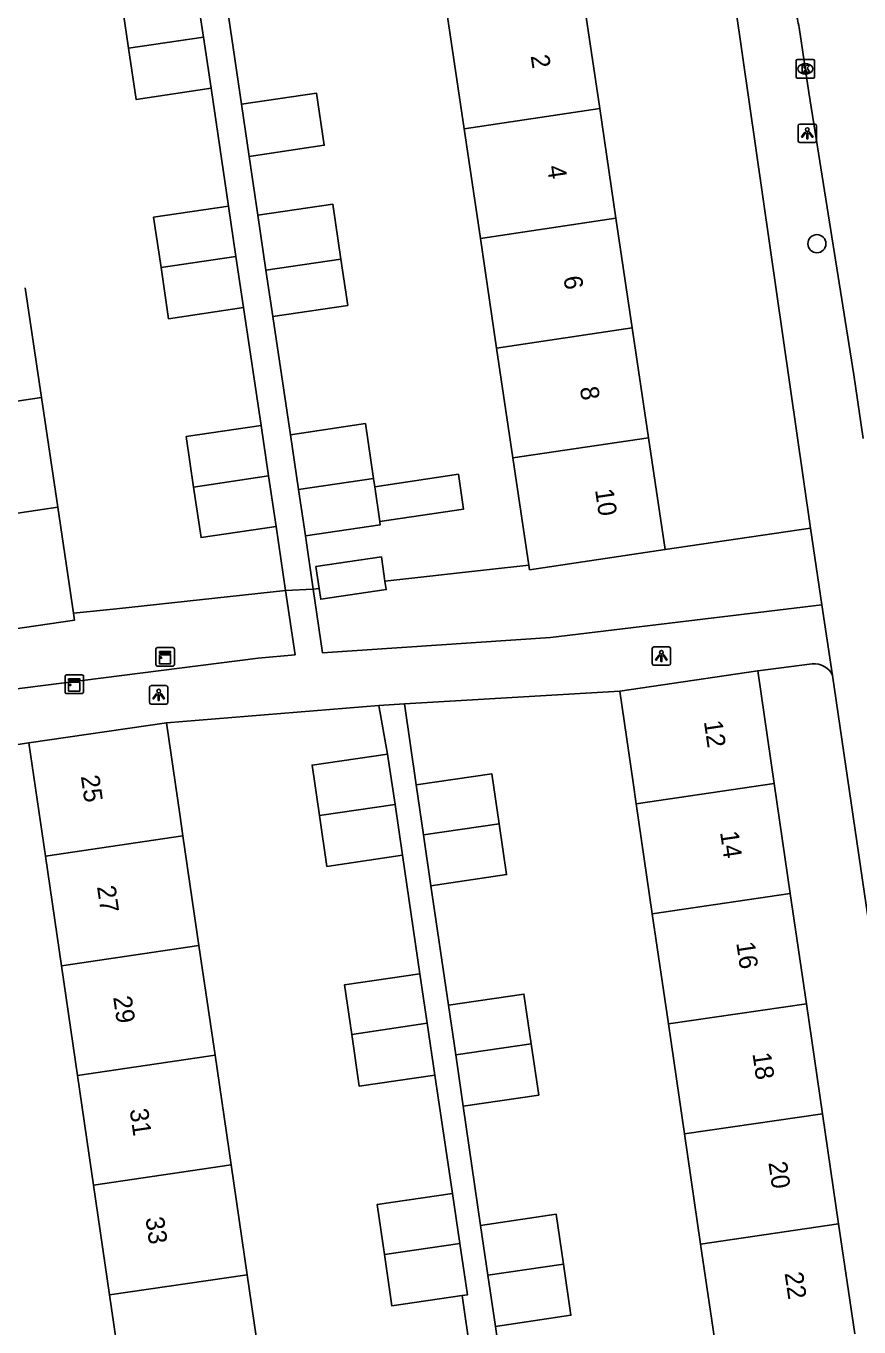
# Model space of a CAD drawing. Extents: x 159053 to 160041, y 380450 to 381422.
# Drawn here: x 159329.7 to 159374.7, y 381049.8 to 381120.2 of the extents above; entities that cross this region are included whole.
import ezdxf

# ---------------------------------------------------------------- set-up
doc = ezdxf.new("R2010")
doc.units = 0
for name, color, linetype in [('IMGEO_Boom', 7, 'Continuous'), ('IMGEO_Groenvoorziening', 7, 'Continuous'), ('IMGEO_Kast', 7, 'Continuous'), ('IMGEO_Kolk', 7, 'Continuous'), ('IMGEO_Lichtpunt', 7, 'Continuous'), ('IMGEO_Muur', 7, 'Continuous'), ('IMGEO_Pand', 7, 'Continuous'), ('IMGEO_Pand_nummerreeks', 7, 'Continuous'), ('IMGEO_Rijbaan_lokaal_open', 7, 'Continuous'), ('IMGEO_Voetpad_open', 7, 'Continuous')]:
    doc.layers.add(name, color=color, linetype=linetype)

msp = doc.modelspace()

# ---------------------------------------------------------------- linework, layer by layer
at = {"layer": 'IMGEO_Boom'}
msp.add_circle((159372.446, 381108.381), 0.489, dxfattribs=at)
at = {"layer": 'IMGEO_Groenvoorziening'}
for points in [[(159372.107, 381092.995), (159364.234, 381091.828)], [(159356.86, 381090.996), (159354.57, 381090.741), (159349.077, 381090.128)], [(159332.23, 381088.384), (159334.548, 381088.632), (159343.701, 381089.611)], [(159345.518, 381089.731), (159345.191, 381089.695)]]:
    msp.add_lwpolyline(points, dxfattribs=at)
at = {"layer": 'IMGEO_Kast'}
for p, q in [((159336.756, 381086.527), (159337.597, 381086.527)), ((159337.597, 381086.527), (159336.756, 381086.527)), ((159336.681, 381085.602), (159336.681, 381086.443)), ((159336.681, 381086.443), (159336.681, 381085.602)), ((159337.681, 381086.452), (159337.681, 381085.611)), ((159337.681, 381085.611), (159337.681, 381086.452)), ((159337.606, 381085.527), (159336.765, 381085.527)), ((159336.765, 381085.527), (159337.606, 381085.527)), ((159331.768, 381084.124), (159331.768, 381084.965)), ((159331.768, 381084.965), (159331.768, 381084.124)), ((159331.843, 381085.049), (159332.684, 381085.049)), ((159332.684, 381085.049), (159331.843, 381085.049)), ((159332.768, 381084.974), (159332.768, 381084.133)), ((159332.768, 381084.133), (159332.768, 381084.974)), ((159332.693, 381084.049), (159331.852, 381084.049)), ((159331.852, 381084.049), (159332.693, 381084.049))]:
    msp.add_line(p, q, dxfattribs=at)
for points in [[(159336.876, 381086.317), (159337.476, 381086.317), (159337.476, 381086.232), (159336.876, 381086.232), (159336.876, 381086.317)], [(159336.876, 381086.142), (159337.476, 381086.142), (159337.476, 381085.653), (159336.876, 381085.653), (159336.876, 381086.142)], [(159331.963, 381084.839), (159332.563, 381084.839), (159332.563, 381084.754), (159331.963, 381084.754), (159331.963, 381084.839)], [(159331.963, 381084.664), (159332.563, 381084.664), (159332.563, 381084.175), (159331.963, 381084.175), (159331.963, 381084.664)]]:
    msp.add_lwpolyline(points, dxfattribs=at)
for centre in [(159336.96, 381085.991), (159332.047, 381084.513)]:
    msp.add_circle(centre, 0.0377, dxfattribs=at)
for centre, start, end in [((159336.759, 381086.449), 92.4484, 184.28452), ((159336.759, 381086.449), 92.4484, 184.28452), ((159337.603, 381086.449), 2.4484, 94.28452), ((159337.603, 381086.449), 2.4484, 94.28452), ((159336.759, 381085.605), 182.4484, 274.28452), ((159336.759, 381085.605), 182.4484, 274.28452), ((159337.603, 381085.605), 272.4484, 4.28452), ((159337.603, 381085.605), 272.4484, 4.28452), ((159331.846, 381084.971), 92.4484, 184.28452), ((159331.846, 381084.971), 92.4484, 184.28452), ((159332.69, 381084.971), 2.4484, 94.28452), ((159332.69, 381084.971), 2.4484, 94.28452), ((159331.846, 381084.127), 182.4484, 274.28452), ((159331.846, 381084.127), 182.4484, 274.28452), ((159332.69, 381084.127), 272.4484, 4.28452), ((159332.69, 381084.127), 272.4484, 4.28452)]:
    msp.add_arc(centre, 0.0779, start, end, dxfattribs=at)
at = {"layer": 'IMGEO_Kolk'}
for p, q in [((159371.32, 381117.416), (159371.32, 381118.268)), ((159371.395, 381118.342), (159372.247, 381118.342)), ((159372.321, 381118.268), (159372.321, 381117.416)), ((159371.831, 381117.562), (159371.806, 381117.562)), ((159371.808, 381118.122), (159371.833, 381118.122)), ((159372.247, 381117.342), (159371.395, 381117.342))]:
    msp.add_line(p, q, dxfattribs=at)
for points in [[(159371.32, 381117.416), (159371.32, 381118.268)], [(159371.395, 381118.342), (159372.247, 381118.342)], [(159372.321, 381118.268), (159372.321, 381117.416)], [(159371.641, 381118.042), (159371.764, 381118.042), (159371.764, 381117.891), (159371.894, 381118.042), (159372.058, 381118.042), (159371.912, 381117.891), (159372.065, 381117.642), (159371.913, 381117.642), (159371.828, 381117.806), (159371.764, 381117.739), (159371.764, 381117.642), (159371.641, 381117.642), (159371.641, 381118.042)], [(159372.247, 381117.342), (159371.395, 381117.342)]]:
    msp.add_lwpolyline(points, dxfattribs=at)
for centre, start, end in [((159371.397, 381118.266), 91.55205, 178.44795), ((159371.397, 381118.266), 91.55205, 178.44795), ((159372.245, 381118.266), 1.55205, 88.44795), ((159372.245, 381118.266), 1.55205, 88.44795), ((159371.397, 381117.418), 181.55205, 268.44795), ((159371.397, 381117.418), 181.55205, 268.44795), ((159372.245, 381117.418), 271.55205, 358.44795), ((159372.245, 381117.418), 271.55205, 358.44795)]:
    msp.add_arc(centre, 0.0765, start, end, dxfattribs=at)
for centre, major_axis, ratio, start_param, end_param in [((159371.807, 381117.842), (-0.387, 0.002), 0.722429, 4.712389, 7.853982), ((159371.832, 381117.842), (-0.39, 0.002), 0.717154, 1.570796, 4.712389)]:
    msp.add_ellipse(centre, major_axis=major_axis, ratio=ratio, start_param=start_param, end_param=end_param, dxfattribs=at)
at = {"layer": 'IMGEO_Lichtpunt'}
for p, q in [((159371.428, 381114.76), (159371.428, 381113.953)), ((159371.428, 381114.76), (159371.428, 381113.953)), ((159372.33, 381114.855), (159371.522, 381114.855)), ((159372.33, 381114.855), (159371.522, 381114.855)), ((159372.424, 381113.953), (159372.424, 381114.76)), ((159372.424, 381113.953), (159372.424, 381114.76)), ((159371.522, 381113.859), (159372.33, 381113.859)), ((159371.522, 381113.859), (159372.33, 381113.859)), ((159364.436, 381086.569), (159363.628, 381086.569)), ((159364.436, 381086.569), (159363.628, 381086.569)), ((159363.534, 381086.474), (159363.534, 381085.667)), ((159363.534, 381086.474), (159363.534, 381085.667)), ((159364.53, 381085.667), (159364.53, 381086.474)), ((159364.53, 381085.667), (159364.53, 381086.474)), ((159363.628, 381085.573), (159364.436, 381085.573)), ((159363.628, 381085.573), (159364.436, 381085.573)), ((159337.238, 381084.469), (159336.43, 381084.469)), ((159337.238, 381084.469), (159336.43, 381084.469)), ((159336.336, 381084.374), (159336.336, 381083.567)), ((159336.336, 381084.374), (159336.336, 381083.567)), ((159337.332, 381083.567), (159337.332, 381084.374)), ((159337.332, 381083.567), (159337.332, 381084.374)), ((159336.43, 381083.473), (159337.238, 381083.473)), ((159336.43, 381083.473), (159337.238, 381083.473))]:
    msp.add_line(p, q, dxfattribs=at)
for points in [[(159371.802, 381114.424), (159371.841, 381114.396), (159371.653, 381114.134), (159371.615, 381114.161), (159371.802, 381114.424)], [(159371.904, 381114.376), (159371.951, 381114.376), (159371.951, 381114.054), (159371.904, 381114.054), (159371.904, 381114.376)], [(159372.014, 381114.396), (159372.052, 381114.423), (159372.239, 381114.161), (159372.2, 381114.133), (159372.014, 381114.396)], [(159363.908, 381086.138), (159363.947, 381086.11), (159363.759, 381085.848), (159363.721, 381085.875), (159363.908, 381086.138)], [(159364.01, 381086.09), (159364.057, 381086.09), (159364.057, 381085.768), (159364.01, 381085.768), (159364.01, 381086.09)], [(159364.12, 381086.11), (159364.158, 381086.137), (159364.345, 381085.875), (159364.306, 381085.847), (159364.12, 381086.11)], [(159336.71, 381084.038), (159336.749, 381084.01), (159336.561, 381083.748), (159336.523, 381083.775), (159336.71, 381084.038)], [(159336.812, 381083.99), (159336.859, 381083.99), (159336.859, 381083.668), (159336.812, 381083.668), (159336.812, 381083.99)], [(159336.922, 381084.01), (159336.96, 381084.037), (159337.147, 381083.775), (159337.108, 381083.747), (159336.922, 381084.01)]]:
    msp.add_lwpolyline(points, dxfattribs=at)
for centre in [(159371.927, 381114.558), (159364.033, 381086.272), (159336.835, 381084.172)]:
    msp.add_circle(centre, 0.0994, dxfattribs=at)
for centre, start, end in [((159371.522, 381114.76), 90, 180), ((159371.522, 381114.76), 90, 180), ((159372.33, 381114.76), 0, 90), ((159372.33, 381114.76), 0, 90), ((159371.522, 381113.953), 180, 270), ((159371.522, 381113.953), 180, 270), ((159372.33, 381113.953), 270, 0), ((159372.33, 381113.953), 270, 360), ((159363.628, 381086.474), 90, 180), ((159363.628, 381086.474), 90, 180), ((159364.436, 381086.474), 0, 90), ((159364.436, 381086.474), 0, 90), ((159363.628, 381085.667), 180, 270), ((159363.628, 381085.667), 180, 270), ((159364.436, 381085.667), 270, 0), ((159364.436, 381085.667), 270, 360), ((159336.43, 381084.374), 90, 180), ((159336.43, 381084.374), 90, 180), ((159337.238, 381084.374), 0, 90), ((159337.238, 381084.374), 0, 90), ((159336.43, 381083.567), 180, 270), ((159336.43, 381083.567), 180, 270), ((159337.238, 381083.567), 270, 0), ((159337.238, 381083.567), 270, 360)]:
    msp.add_arc(centre, 0.0946, start, end, dxfattribs=at)
at = {"layer": 'IMGEO_Muur'}
for points in [[(159361.777, 381084.175), (159350.126, 381083.478)], [(159337.25, 381082.465), (159348.751, 381083.396)]]:
    msp.add_lwpolyline(points, dxfattribs=at)
at = {"layer": 'IMGEO_Pand'}
for points in [[(159335.2, 381118.957), (159334.796, 381121.68), (159338.851, 381122.282)], [(159338.851, 381122.282), (159339.255, 381119.559)], [(159360.696, 381115.69), (159359.798, 381121.745)], [(159352.462, 381120.658), (159353.36, 381114.602)], [(159339.255, 381119.559), (159335.2, 381118.957)], [(159339.666, 381116.792), (159335.611, 381116.19), (159335.2, 381118.957)], [(159339.255, 381119.559), (159339.666, 381116.792)], [(159341.321, 381115.924), (159345.378, 381116.523), (159345.795, 381113.703), (159341.738, 381113.104)], [(159341.738, 381113.104), (159341.321, 381115.924)], [(159360.696, 381115.69), (159353.36, 381114.602)], [(159361.576, 381109.755), (159360.696, 381115.69)], [(159353.36, 381114.602), (159354.24, 381108.667)], [(159346.696, 381107.548), (159346.258, 381110.517), (159342.201, 381109.918)], [(159336.96, 381107.087), (159336.556, 381109.81), (159340.611, 381110.412)], [(159340.611, 381110.412), (159341.015, 381107.689)], [(159342.201, 381109.918), (159342.64, 381106.947)], [(159361.576, 381109.755), (159354.24, 381108.667)], [(159362.456, 381103.82), (159361.576, 381109.755)], [(159354.24, 381108.667), (159355.12, 381102.732)], [(159341.015, 381107.689), (159336.96, 381107.087)], [(159341.426, 381104.922), (159341.015, 381107.689)], [(159336.96, 381107.087), (159337.371, 381104.32), (159341.426, 381104.922)], [(159342.64, 381106.947), (159346.696, 381107.548)], [(159343.009, 381104.447), (159342.64, 381106.947)], [(159346.696, 381107.548), (159347.066, 381105.046), (159343.009, 381104.447)], [(159330.498, 381100.062), (159329.618, 381105.998)], [(159355.12, 381102.732), (159362.456, 381103.82)], [(159363.336, 381097.885), (159362.456, 381103.82)], [(159356, 381096.797), (159355.12, 381102.732)], [(159323.098, 381098.964), (159330.498, 381100.062)], [(159330.498, 381100.062), (159331.378, 381094.127)], [(159338.725, 381095.217), (159338.321, 381097.941), (159342.376, 381098.543)], [(159342.376, 381098.543), (159342.78, 381095.819)], [(159343.961, 381098.048), (159348.018, 381098.647), (159348.456, 381095.678)], [(159344.4, 381095.077), (159343.961, 381098.048)], [(159363.336, 381097.885), (159356, 381096.797)], [(159364.234, 381091.828), (159363.336, 381097.885)], [(159356, 381096.797), (159356.86, 381090.996)], [(159338.725, 381095.217), (159342.78, 381095.819)], [(159342.78, 381095.819), (159343.186, 381093.082)], [(159348.456, 381095.678), (159344.4, 381095.077)], [(159348.522, 381095.235), (159348.456, 381095.678)], [(159348.8, 381093.353), (159353.326, 381094.023), (159353.047, 381095.904), (159348.522, 381095.235)], [(159343.186, 381093.082), (159339.131, 381092.48), (159338.725, 381095.217)], [(159344.769, 381092.577), (159344.4, 381095.077)], [(159348.522, 381095.235), (159348.8, 381093.353)], [(159331.378, 381094.127), (159323.978, 381093.029)], [(159332.23, 381088.384), (159331.378, 381094.127)], [(159344.769, 381092.577), (159348.826, 381093.176), (159348.8, 381093.353)], [(159356.86, 381090.996), (159356.898, 381090.74), (159364.234, 381091.828)], [(159349.077, 381090.128), (159348.885, 381091.432), (159345.344, 381090.909), (159345.518, 381089.731)], [(159349.077, 381090.128), (159349.146, 381089.663), (159345.605, 381089.14), (159345.518, 381089.731)], [(159324.884, 381086.922), (159332.284, 381088.02), (159332.23, 381088.384)], [(159369.242, 381085.268), (159361.777, 381084.175)], [(159369.242, 381085.268), (159370.133, 381079.176)], [(159361.777, 381084.175), (159362.501, 381079.228), (159362.668, 381078.084)], [(159337.25, 381082.465), (159329.808, 381081.376)], [(159338.145, 381076.348), (159337.974, 381077.518), (159337.25, 381082.465)], [(159329.808, 381081.376), (159330.704, 381075.253)], [(159349.222, 381080.771), (159345.136, 381080.173), (159345.537, 381077.436)], [(159349.623, 381078.037), (159349.222, 381080.771)], [(159355.25, 381076.999), (159354.853, 381079.706), (159350.766, 381079.108)], [(159350.766, 381079.108), (159351.162, 381076.401)], [(159362.668, 381078.084), (159370.133, 381079.176)], [(159370.133, 381079.176), (159371.005, 381073.219)], [(159362.668, 381078.084), (159363.54, 381072.127)], [(159345.537, 381077.436), (159349.623, 381078.037)], [(159345.537, 381077.436), (159345.939, 381074.692), (159350.025, 381075.29)], [(159350.025, 381075.29), (159349.623, 381078.037)], [(159355.25, 381076.999), (159351.162, 381076.401)], [(159351.566, 381073.646), (159355.653, 381074.244), (159355.25, 381076.999)], [(159330.704, 381075.253), (159338.145, 381076.348)], [(159339.014, 381070.412), (159338.145, 381076.348)], [(159351.162, 381076.401), (159351.566, 381073.646)], [(159330.704, 381075.253), (159331.572, 381069.317)], [(159363.54, 381072.127), (159371.005, 381073.219)], [(159371.005, 381073.219), (159371.877, 381067.262)], [(159363.54, 381072.127), (159364.412, 381066.17)], [(159339.014, 381070.412), (159331.572, 381069.317)], [(159339.883, 381064.475), (159339.014, 381070.412)], [(159331.572, 381069.317), (159332.441, 381063.38)], [(159350.972, 381068.878), (159346.886, 381068.28), (159347.278, 381065.603)], [(159351.363, 381066.21), (159350.972, 381068.878)], [(159356.993, 381065.085), (159356.598, 381067.779), (159352.511, 381067.181)], [(159352.511, 381067.181), (159352.906, 381064.487)], [(159371.877, 381067.262), (159364.412, 381066.17)], [(159371.877, 381067.262), (159372.748, 381061.306)], [(159347.278, 381065.603), (159351.363, 381066.21)], [(159351.775, 381063.397), (159351.363, 381066.21)], [(159364.412, 381066.17), (159365.283, 381060.214)], [(159347.278, 381065.603), (159347.689, 381062.799), (159351.775, 381063.397)], [(159352.906, 381064.487), (159356.993, 381065.085)], [(159353.311, 381061.719), (159357.398, 381062.317), (159356.993, 381065.085)], [(159339.883, 381064.475), (159332.441, 381063.38)], [(159340.751, 381058.538), (159339.883, 381064.475)], [(159352.906, 381064.487), (159353.311, 381061.719)], [(159332.441, 381063.38), (159333.31, 381057.443)], [(159365.283, 381060.214), (159372.748, 381061.306)], [(159372.748, 381061.306), (159373.62, 381055.349)], [(159365.283, 381060.214), (159366.155, 381054.257)], [(159333.31, 381057.443), (159340.751, 381058.538)], [(159341.62, 381052.601), (159340.751, 381058.538)], [(159334.178, 381051.506), (159333.31, 381057.443)], [(159352.737, 381056.99), (159348.651, 381056.392), (159349.046, 381053.694)], [(159353.132, 381054.295), (159352.737, 381056.99)], [(159358.736, 381053.172), (159358.341, 381055.866), (159354.254, 381055.268)], [(159354.254, 381055.268), (159354.649, 381052.574)], [(159373.62, 381055.349), (159366.155, 381054.257)], [(159373.62, 381055.349), (159374.491, 381049.393)], [(159349.046, 381053.694), (159353.132, 381054.295)], [(159353.257, 381051.468), (159353.54, 381051.509), (159353.132, 381054.295)], [(159366.155, 381054.257), (159367.026, 381048.302)], [(159349.046, 381053.694), (159349.454, 381050.911), (159353.257, 381051.468)], [(159354.649, 381052.574), (159358.736, 381053.172)], [(159355.054, 381049.806), (159359.141, 381050.404), (159358.736, 381053.172)], [(159341.62, 381052.601), (159334.178, 381051.506)], [(159342.489, 381046.664), (159341.62, 381052.601)], [(159354.649, 381052.574), (159355.054, 381049.806)], [(159334.178, 381051.506), (159335.047, 381045.569)]]:
    msp.add_lwpolyline(points, dxfattribs=at)
at = {"layer": 'IMGEO_Rijbaan_lokaal_open'}
msp.add_lwpolyline([(159374.956, 381097.837), (159374.453, 381101.279), (159372.016, 381116.567), (159371.48, 381120.071)], dxfattribs=at)
msp.add_arc((159367.251, 381119.5), 4.267, 7.68473, 20.38776, dxfattribs=at)
at = {"layer": 'IMGEO_Voetpad_open'}
for points in [[(159341.321, 381115.924), (159340.268, 381123.048)], [(159368.043, 381121.201), (159372.107, 381092.995)], [(159339.666, 381116.792), (159340.611, 381110.412)], [(159342.201, 381109.918), (159341.738, 381113.104)], [(159341.426, 381104.922), (159342.376, 381098.543)], [(159343.961, 381098.048), (159343.009, 381104.447)], [(159343.186, 381093.082), (159343.701, 381089.611)], [(159372.706, 381088.84), (159372.107, 381092.995)], [(159345.191, 381089.695), (159344.769, 381092.577)], [(159343.701, 381089.611), (159344.216, 381086.143), (159342.223, 381085.964), (159323.192, 381083.535)], [(159343.701, 381089.611), (159345.191, 381089.695)], [(159345.191, 381089.695), (159345.703, 381086.245), (159358.026, 381087.077), (159372.706, 381088.84)], [(159373.296, 381085.027), (159372.706, 381088.84)], [(159372.195, 381085.642), (159369.242, 381085.268)], [(159388.726, 380978.358), (159385.752, 381000), (159373.296, 381085.027)], [(159350.126, 381083.478), (159361.777, 381084.175)], [(159337.25, 381082.465), (159348.751, 381083.396)], [(159348.751, 381083.396), (159350.126, 381083.478)], [(159348.751, 381083.396), (159349.222, 381080.771)], [(159350.766, 381079.108), (159350.126, 381083.478)], [(159329.808, 381081.376), (159324.411, 381080.569)], [(159350.025, 381075.29), (159350.972, 381068.878)], [(159352.511, 381067.181), (159351.566, 381073.646)], [(159351.775, 381063.397), (159352.737, 381056.99)], [(159354.254, 381055.268), (159353.311, 381061.719)], [(159353.257, 381051.468), (159354.151, 381045.198)], [(159355.997, 381043.355), (159355.054, 381049.806)]]:
    msp.add_lwpolyline(points, dxfattribs=at)
msp.add_arc((159372.324, 381084.581), 1.069, 24.67534, 96.95068, dxfattribs=at)

# ---------------------------------------------------------------- texts
at = {"layer": 'IMGEO_Pand_nummerreeks'}
for s, rotation, p in [('2', 278.43419, (159356.956, 381118.546)), ('4', 278.43419, (159357.844, 381112.561)), ('6', 278.43419, (159358.731, 381106.577)), ('8', 278.43419, (159359.619, 381100.59)), ('10', 278.43419, (159360.439, 381095.063)), ('12', 278.32428, (159366.328, 381082.531)), ('25', 278.32417, (159332.619, 381079.571)), ('14', 278.32428, (159367.204, 381076.541)), ('27', 278.32417, (159333.493, 381073.594)), ('16', 278.32428, (159368.08, 381070.554)), ('29', 278.32417, (159334.368, 381067.618)), ('18', 278.32428, (159368.957, 381064.564)), ('31', 278.32417, (159335.258, 381061.529)), ('20', 278.32428, (159369.819, 381058.667)), ('33', 278.32417, (159336.116, 381055.665)), ('22', 278.32428, (159370.695, 381052.686))]:
    msp.add_text(s, height=1, rotation=rotation, dxfattribs=at).set_placement(p)

doc.saveas('drawing.dxf')
